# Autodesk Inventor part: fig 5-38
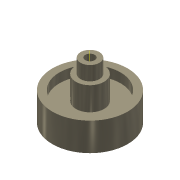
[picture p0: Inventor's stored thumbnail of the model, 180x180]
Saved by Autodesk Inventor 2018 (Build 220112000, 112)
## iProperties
Shininess: 65.0
Length Units: 11269
Angle Units: 11279
Time Units: 11290
Mass Units: 11283
Length Display Precision: 3
Angle Display Precision: 2
Created: 2001-11
Part Number: fig 5-38
Document SubType Name: Modeling
Designer: Renu Muthoo
Density: 1 g/cm^3
Material: Generic
Appearance: Metal-Titanium (Polished)
Density: 0.0
Volumn: 0.0
Area: 0.0
PropertySet Name: Model Information
Control State: 0
Master: False
Checked Out: False
Author: Renu Muthoo
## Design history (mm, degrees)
sketch "Sketch1"
  geometry: L1 (2.694, 30.112)-(5.194, 30.112); L2 (5.194, 30.112)-(5.194, 22.612); L3 (5.194, 22.612)-(7.694, 22.612); L4 (7.694, 22.612)-(7.694, 10.112); L5 (7.694, 10.112)-(16.444, 10.112); L6 (16.444, 10.112)-(16.444, 15.112); L7 (16.444, 15.112)-(20.194, 15.112); L8 (0.194, -4.034)-(0.194, 25.966); L9 (2.694, 30.112)-(2.694, 0.112); L10 (2.694, 0.112)-(20.194, 0.112); L11 (20.194, 0.112)-(20.194, 15.112)
  constraints: 22 end point, 7 parallel, 2 perpendicular, 1 horizontal
  dimensions: "d0" = 5 diameter of L9 L8; "d1" = 10 diameter of L2 L8; "d2" = 15 diameter of L4 L8; "d3" = 32.5 diameter of L6 L8; "d4" = 40 diameter of L11 L8; "d5" = 15 distance of L10.end L7.end; "d6" = 22.5 distance between parallel lines of L3 L10; "d7" = 30 distance between parallel lines of L1 L10; "d8" = 10 distance between parallel lines of L10 L5
revolve "Revolution1" sketch "Sketch1" stored, may be unused: angle "d9" = 90 deg
workaxis "Work Axis1"
node "Sketch3"
workaxis "Work Axis4"
body "Solid1"
